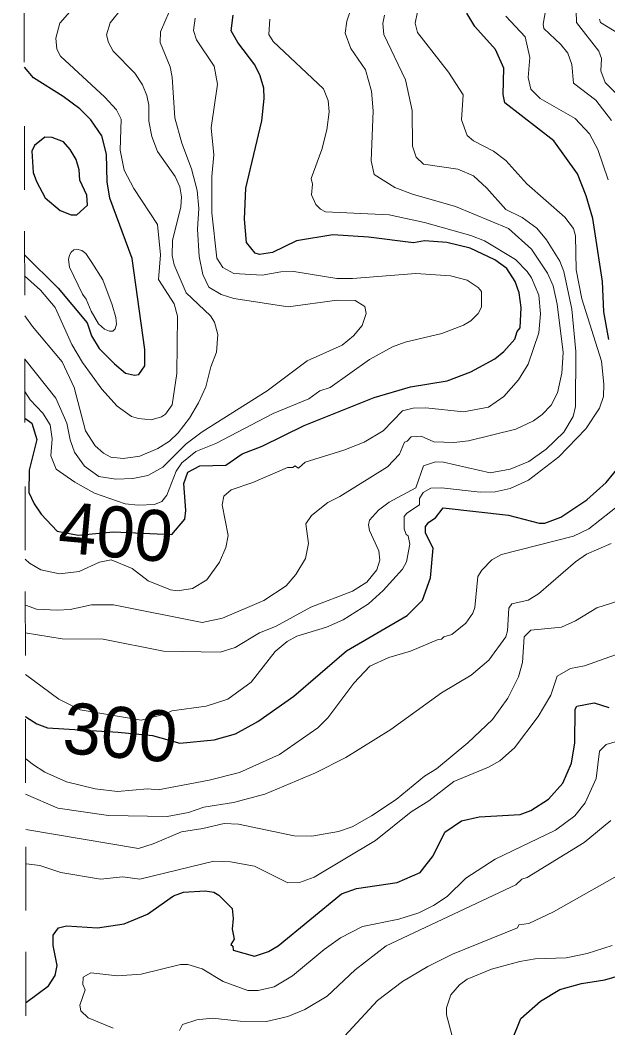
# Model space of a CAD drawing. Extents: x 474.5 to 500, y 7345.7 to 7373.4.
# Drawn here: x 474.522 to 475.444, y 7368.127 to 7369.706 of the extents above; entities that cross this region are included whole.
import ezdxf
from ezdxf.enums import TextEntityAlignment as Align

# ---------------------------------------------------------------- set-up
doc = ezdxf.new("R2010")
doc.units = 0
doc.header["$LTSCALE"] = 0.032
doc.linetypes.add('SHORT_DASHED', pattern=[2.7, 1.5, -1.2])
for name, color, linetype, lineweight in [('1', 7, 'Continuous', 25), ('2', 7, 'Continuous', 13), ('22', 7, 'SHORT_DASHED', 13)]:
    doc.layers.add(name, color=color, linetype=linetype, lineweight=lineweight)
doc.layers.add('61', color=7, linetype='Continuous')

msp = doc.modelspace()

# ---------------------------------------------------------------- linework, layer by layer
at = {"layer": '1'}
for points in [[(474.5297, 7369.0823), (474.5404, 7369.0743), (474.5484, 7369.0487), (474.5365, 7369.001), (474.536, 7368.9656), (474.5441, 7368.9481), (474.5553, 7368.9317), (474.5803, 7368.9051), (474.6132, 7368.8991), (474.6687, 7368.9043), (474.76, 7368.9001), (474.7807, 7368.9242), (474.7822, 7368.9378), (474.7792, 7368.9801), (474.7852, 7368.9977), (474.8039, 7369.0077), (474.8448, 7369.0087), (474.8706, 7369.0263), (474.9018, 7369.0383), (474.9677, 7369.071), (475.0773, 7369.1149), (475.1344, 7369.1314), (475.1918, 7369.141), (475.2292, 7369.155), (475.2667, 7369.1754), (475.2811, 7369.1868), (475.2981, 7369.206), (475.3017, 7369.2183), (475.3064, 7369.224), (475.3081, 7369.2559), (475.3049, 7369.2786), (475.2989, 7369.2968), (475.2856, 7369.3172), (475.2666, 7369.3304), (475.2279, 7369.3486), (475.1915, 7369.3579), (475.1567, 7369.3603), (475.1392, 7369.3572), (475.0684, 7369.366), (475.0125, 7369.3699), (474.9557, 7369.3604), (474.9178, 7369.3422), (474.8977, 7369.3389), (474.8911, 7369.3409), (474.8774, 7369.3577), (474.874, 7369.3942), (474.8764, 7369.443), (474.9011, 7369.5486), (474.9051, 7369.5834), (474.9044, 7369.5999), (474.8987, 7369.6188), (474.8901, 7369.6361), (474.8638, 7369.6712), (474.8533, 7369.6894), (474.8564, 7369.7143)], [(475.4455, 7369.2058), (475.438, 7369.2489), (475.4356, 7369.2968), (475.4204, 7369.3954), (475.41, 7369.4308), (475.3965, 7369.4656), (475.3592, 7369.5173), (475.2824, 7369.5769), (475.2801, 7369.5898), (475.2807, 7369.631), (475.2681, 7369.6603), (475.2352, 7369.6964), (475.2227, 7369.7173)], [(474.5293, 7369.3382), (474.5821, 7369.2861), (474.6275, 7369.2319), (474.634, 7369.2112), (474.6463, 7369.1918), (474.6704, 7369.1675), (474.6876, 7369.1529), (474.7014, 7369.1498), (474.7083, 7369.1508), (474.7177, 7369.1644), (474.7176, 7369.1899), (474.6978, 7369.3329), (474.6627, 7369.4272), (474.6586, 7369.4528), (474.6578, 7369.4962), (474.6505, 7369.5249), (474.6331, 7369.5501), (474.6158, 7369.5675), (474.5895, 7369.5868), (474.5432, 7369.6157), (474.5288, 7369.6323)], [(474.5306, 7368.6147), (474.5313, 7368.6142), (474.5482, 7368.6033), (474.5649, 7368.5968), (474.6758, 7368.5901), (474.7297, 7368.5847), (474.7726, 7368.5731), (474.8268, 7368.5781), (474.8599, 7368.5875), (474.895, 7368.6068), (474.9517, 7368.6467), (475.0341, 7368.7177), (475.1291, 7368.7732), (475.1532, 7368.7972), (475.166, 7368.8323), (475.17, 7368.8785), (475.1582, 7368.9022), (475.1581, 7368.9125), (475.1633, 7368.9195), (475.1738, 7368.9262), (475.1855, 7368.9419), (475.2885, 7368.9304), (475.3364, 7368.9176), (475.3452, 7368.9177), (475.3705, 7368.9273), (475.4112, 7368.9544), (475.4412, 7368.9813), (475.4773, 7369.0255)], [(474.5314, 7368.1664), (474.532, 7368.1669), (474.5667, 7368.1923), (474.5773, 7368.2086), (474.5804, 7368.2243), (474.5741, 7368.2557), (474.5741, 7368.2722), (474.5824, 7368.2834), (474.5948, 7368.2865), (474.6434, 7368.2834), (474.6855, 7368.29), (474.7222, 7368.3048), (474.7626, 7368.3337), (474.7783, 7368.3392), (474.8123, 7368.3413), (474.8261, 7368.3392), (474.8339, 7368.3346), (474.8547, 7368.3137), (474.8564, 7368.298), (474.8549, 7368.2814), (474.8579, 7368.2659), (474.8527, 7368.2572), (474.8557, 7368.2549), (474.8566, 7368.2484), (474.8899, 7368.239), (474.9117, 7368.2464), (474.9272, 7368.2553), (475.0264, 7368.3368), (475.0498, 7368.3449), (475.1136, 7368.3544), (475.1496, 7368.3701), (475.1699, 7368.3964), (475.1886, 7368.4335), (475.2143, 7368.4513), (475.2423, 7368.4572), (475.3067, 7368.4613), (475.3235, 7368.4674), (475.3511, 7368.4852), (475.3736, 7368.5102), (475.3869, 7368.5416), (475.3925, 7368.5734), (475.3926, 7368.6262), (475.3956, 7368.631), (475.4228, 7368.6359), (475.4455, 7368.6288)], [(475.2937, 7368.1065), (475.3075, 7368.1415), (475.3386, 7368.1686), (475.369, 7368.187), (475.403, 7368.1963), (475.4391, 7368.2021), (475.4732, 7368.2121)]]:
    msp.add_lwpolyline(points, dxfattribs=at)
msp.add_lwpolyline([(474.5428, 7369.4674), (474.5478, 7369.4533), (474.5617, 7369.428), (474.5849, 7369.4077), (474.6023, 7369.4012), (474.6111, 7369.4011), (474.6278, 7369.4162), (474.6267, 7369.4321), (474.6157, 7369.4555), (474.6148, 7369.4715), (474.61, 7369.4877), (474.6008, 7369.5035), (474.5902, 7369.5157), (474.5725, 7369.5222), (474.5608, 7369.523), (474.5447, 7369.5097), (474.5406, 7369.5007)], close=True, dxfattribs=at)
at = {"layer": '2'}
msp.add_line((474.5414, 7368.5398), (474.5307, 7368.5488), dxfattribs=at)
for points in [[(474.5293, 7369.3054), (474.5542, 7369.2828), (474.5769, 7369.2556), (474.6035, 7369.1979), (474.6198, 7369.1697), (474.6502, 7369.1279), (474.6744, 7369.1012), (474.697, 7369.0852), (474.708, 7369.0816), (474.7278, 7369.0795), (474.7439, 7369.0844), (474.7501, 7369.0887), (474.7608, 7369.1032), (474.7679, 7369.1524), (474.7688, 7369.242), (474.7637, 7369.2618), (474.7393, 7369.2997), (474.7424, 7369.3386), (474.7376, 7369.3858), (474.7007, 7369.4424), (474.6853, 7369.4711), (474.6793, 7369.5023), (474.6809, 7369.551), (474.6733, 7369.5656), (474.6551, 7369.5857), (474.5855, 7369.6497), (474.5798, 7369.6609), (474.5781, 7369.6781), (474.5845, 7369.7017), (474.621, 7369.7434)], [(474.5303, 7368.7893), (474.5324, 7368.7886), (474.5481, 7368.7832), (474.5805, 7368.7812), (474.6009, 7368.7827), (474.6341, 7368.7899), (474.6688, 7368.7899), (474.8077, 7368.7621), (474.8395, 7368.7689), (474.9046, 7368.7965), (474.9394, 7368.8196), (474.9544, 7368.8374), (474.9696, 7368.8623), (474.9745, 7368.8859), (474.9706, 7368.9165), (474.979, 7368.93), (475.0046, 7368.9502), (475.0238, 7368.9597), (475.0987, 7369.0063), (475.1171, 7369.026), (475.1253, 7369.045), (475.1295, 7369.0463), (475.1354, 7369.0529), (475.1514, 7369.054), (475.1711, 7369.0453), (475.2027, 7369.0444), (475.2253, 7369.0469), (475.2998, 7369.0652), (475.3274, 7369.0784), (475.3412, 7369.0882), (475.3554, 7369.1029), (475.3652, 7369.122), (475.3718, 7369.153), (475.3742, 7369.1854), (475.3647, 7369.2612), (475.3583, 7369.2899), (475.3494, 7369.3095), (475.3241, 7369.3473), (475.2883, 7369.3797), (475.205, 7369.4142), (475.1374, 7369.4334), (475.1101, 7369.4441), (475.0775, 7369.4641), (475.0726, 7369.4857), (475.0759, 7369.5639), (475.0734, 7369.5951), (475.064, 7369.6282), (475.0409, 7369.6617), (475.032, 7369.6859), (475.0349, 7369.7049), (475.0503, 7369.751)], [(475.4499, 7369.5488), (475.425, 7369.5807), (475.3904, 7369.6075), (475.3876, 7369.6369), (475.3815, 7369.6544), (475.3702, 7369.6682), (475.3437, 7369.693), (475.3425, 7369.6999), (475.3505, 7369.7454)], [(474.6826, 7369.726), (474.6633, 7369.7022), (474.6579, 7369.6835), (474.6607, 7369.6714), (474.6681, 7369.6577), (474.7021, 7369.6233), (474.7143, 7369.6047), (474.7209, 7369.5883), (474.724, 7369.5728), (474.7241, 7369.5481), (474.729, 7369.5241), (474.7379, 7369.5002), (474.7654, 7369.461), (474.7727, 7369.4451), (474.7751, 7369.4295), (474.7744, 7369.4136), (474.7611, 7369.3609), (474.7608, 7369.3375), (474.7637, 7369.3229), (474.7824, 7369.279), (474.8206, 7369.243), (474.8269, 7369.2328), (474.8325, 7369.2135), (474.83, 7369.1859), (474.8214, 7369.1628), (474.8137, 7369.1315), (474.8021, 7369.1064), (474.7877, 7369.0825), (474.7699, 7369.0594), (474.7566, 7369.0465), (474.7381, 7369.0346), (474.71, 7369.023), (474.6838, 7369.0189), (474.6643, 7369.0214), (474.653, 7369.0274), (474.6399, 7369.0391), (474.6249, 7369.0623), (474.6068, 7369.1304), (474.5883, 7369.1706), (474.5417, 7369.2258), (474.5294, 7369.2429), (474.5294, 7369.243)], [(474.5296, 7369.1746), (474.5782, 7369.1136), (474.5957, 7369.0745), (474.6006, 7369.0482), (474.6074, 7369.029), (474.6232, 7369.0073), (474.6457, 7368.9911), (474.6721, 7368.987), (474.6991, 7368.9878), (474.7227, 7368.9926), (474.7458, 7369.0055), (474.7824, 7369.0422), (474.8075, 7369.0607), (474.9099, 7369.125), (474.9722, 7369.1724), (475.0272, 7369.1969), (475.0451, 7369.2115), (475.0589, 7369.2277), (475.0648, 7369.2466), (475.0629, 7369.2575), (475.0477, 7369.267), (475.0195, 7369.2671), (474.9424, 7369.2567), (474.8575, 7369.27), (474.8376, 7369.2764), (474.8184, 7369.2877), (474.8086, 7369.3075), (474.8029, 7369.3358), (474.8006, 7369.3784), (474.8023, 7369.4108), (474.7997, 7369.4391), (474.7912, 7369.4731), (474.776, 7369.5133), (474.7648, 7369.5532), (474.7608, 7369.617), (474.7576, 7369.6329), (474.7417, 7369.6712), (474.7425, 7369.6881), (474.7562, 7369.7192)], [(474.5297, 7369.1241), (474.538, 7369.1109), (474.5577, 7369.0903), (474.5692, 7369.0718), (474.5725, 7369.0502), (474.5702, 7369.0233), (474.5785, 7369.0026), (474.6082, 7368.982), (474.6389, 7368.9646), (474.6867, 7368.9479), (474.7071, 7368.946), (474.7332, 7368.9473), (474.7446, 7368.9517), (474.7525, 7368.9619), (474.7669, 7368.9992), (474.7758, 7369.0124), (474.798, 7369.0299), (474.8292, 7369.0427), (474.9193, 7369.0898), (474.9751, 7369.1129), (474.9922, 7369.125), (475.0086, 7369.1304), (475.07, 7369.1743), (475.1064, 7369.1942), (475.1264, 7369.2016), (475.1838, 7369.2152), (475.2176, 7369.2282), (475.2291, 7369.235), (475.2409, 7369.2463), (475.2459, 7369.2564), (475.2458, 7369.2811), (475.2408, 7369.2871), (475.2234, 7369.2989), (475.1974, 7369.3054), (475.1427, 7369.3093), (475.0437, 7369.3014), (475.0191, 7369.3014), (474.9513, 7369.3125), (474.9312, 7369.3116), (474.9016, 7369.3063), (474.8575, 7369.3092), (474.8399, 7369.3185), (474.8308, 7369.3334), (474.823, 7369.4044), (474.823, 7369.4614), (474.8261, 7369.4949), (474.8221, 7369.5374), (474.8317, 7369.606), (474.8268, 7369.634), (474.7989, 7369.6756), (474.7943, 7369.6899), (474.7966, 7369.7095)], [(474.5301, 7368.8612), (474.5369, 7368.8549), (474.5544, 7368.8445), (474.584, 7368.8386), (474.6149, 7368.842), (474.6468, 7368.8565), (474.665, 7368.8601), (474.698, 7368.8468), (474.7229, 7368.8272), (474.7582, 7368.8134), (474.769, 7368.8115), (474.7927, 7368.8156), (474.8148, 7368.8289), (474.835, 7368.8564), (474.8446, 7368.8798), (474.8485, 7368.8982), (474.839, 7368.9464), (474.8419, 7368.9601), (474.8534, 7368.9702), (474.8871, 7368.9815), (474.9418, 7369.005), (474.9499, 7369.0052), (474.9533, 7369.0075), (474.9586, 7369.004), (474.9692, 7369.0134), (475.0302, 7369.0323), (475.0621, 7369.0447), (475.0915, 7369.0623), (475.1221, 7369.0941), (475.1387, 7369.0978), (475.1587, 7369.0987), (475.2176, 7369.0924), (475.2569, 7369.0995), (475.2811, 7369.1165), (475.304, 7369.1425), (475.319, 7369.1671), (475.3358, 7369.2162), (475.3383, 7369.246), (475.3356, 7369.2752), (475.3242, 7369.3024), (475.3177, 7369.3122), (475.299, 7369.331), (475.2508, 7369.3602), (475.2293, 7369.3685), (475.1565, 7369.389), (475.1009, 7369.401), (475.0011, 7369.4059), (474.9931, 7369.4098), (474.986, 7369.4174), (474.9792, 7369.4322), (474.9807, 7369.449), (474.9786, 7369.4581), (474.9954, 7369.5033), (475.0032, 7369.5342), (475.0072, 7369.5624), (475.0056, 7369.5805), (474.9983, 7369.5988), (474.9191, 7369.6726), (474.9125, 7369.684), (474.914, 7369.708)], [(475.0936, 7369.7142), (475.0911, 7369.7011), (475.0927, 7369.684), (475.1268, 7369.6127), (475.1373, 7369.5648), (475.1374, 7369.5085), (475.1433, 7369.4914), (475.1549, 7369.4807), (475.2089, 7369.4729), (475.2335, 7369.4621), (475.2543, 7369.4428), (475.2841, 7369.4096), (475.3098, 7369.3969), (475.3328, 7369.3801), (475.3481, 7369.3617), (475.3686, 7369.3284), (475.3751, 7369.3122), (475.3878, 7369.2532), (475.3941, 7369.187), (475.3934, 7369.1005), (475.3896, 7369.0852), (475.3749, 7369.0602), (475.3475, 7369.0337), (475.3202, 7369.0147), (475.2907, 7369.0022), (475.2594, 7368.9966), (475.1865, 7369.0134), (475.1735, 7369.0141), (475.1549, 7369.0076), (475.143, 7368.973), (475.1008, 7368.9505), (475.0842, 7368.9379), (475.0703, 7368.9224), (475.0687, 7368.9152), (475.0701, 7368.9062), (475.0851, 7368.8746), (475.0863, 7368.8597), (475.0819, 7368.8448), (475.0659, 7368.8254), (475.0437, 7368.8113), (474.9783, 7368.7862), (474.9228, 7368.756), (474.8977, 7368.7459), (474.8594, 7368.7228), (474.836, 7368.7158), (474.7471, 7368.7174), (474.6525, 7368.7357), (474.5882, 7368.7366), (474.5303, 7368.7458)], [(474.5304, 7368.6806), (474.5827, 7368.6421), (474.6164, 7368.6254), (474.7119, 7368.6092), (474.7494, 7368.6183), (474.7603, 7368.6236), (474.814, 7368.6309), (474.8478, 7368.642), (474.8845, 7368.6687), (474.922, 7368.7165), (474.9409, 7368.7322), (474.9564, 7368.7408), (475.003, 7368.7548), (475.0288, 7368.766), (475.0684, 7368.7911), (475.0917, 7368.8121), (475.1219, 7368.8455), (475.1285, 7368.857), (475.1333, 7368.8848), (475.1311, 7368.8978), (475.1279, 7368.9001), (475.1246, 7368.9089), (475.1246, 7368.9284), (475.1286, 7368.9335), (475.1484, 7368.9467), (475.1485, 7368.9566), (475.1546, 7368.9659), (475.1663, 7368.9726), (475.183, 7368.9734), (475.2436, 7368.9666), (475.2671, 7368.9671), (475.2907, 7368.9719), (475.3197, 7368.9853), (475.3672, 7369.0215), (475.4094, 7369.0654), (475.4312, 7369.098), (475.4372, 7369.1162), (475.438, 7369.1359), (475.4342, 7369.1715), (475.4033, 7369.2693), (475.3942, 7369.3151), (475.3935, 7369.3684), (475.39, 7369.3797), (475.3768, 7369.3976), (475.3168, 7369.4496), (475.2842, 7369.4863), (475.2647, 7369.5009), (475.2336, 7369.5172), (475.2235, 7369.5255), (475.2147, 7369.55), (475.217, 7369.5893), (475.1943, 7369.6248), (475.1453, 7369.6869), (475.1421, 7369.7017), (475.1453, 7369.7193)], [(475.2841, 7369.7124), (475.3144, 7369.6799), (475.3217, 7369.6478), (475.3192, 7369.6163), (475.3232, 7369.5981), (475.3378, 7369.5836), (475.393, 7369.5522), (475.4154, 7369.5283), (475.4285, 7369.5037), (475.4445, 7369.4558)], [(475.3942, 7369.7209), (475.3949, 7369.7028), (475.4297, 7369.6577), (475.4342, 7369.6462), (475.4333, 7369.6266), (475.44, 7369.6084), (475.4796, 7369.5693)], [(475.477, 7369.6754), (475.4327, 7369.7024), (475.4309, 7369.7077)], [(475.4659, 7368.9495), (475.4145, 7368.9088), (475.3903, 7368.8972), (475.2772, 7368.8687), (475.262, 7368.8603), (475.2463, 7368.8441), (475.2404, 7368.8341), (475.2354, 7368.7857), (475.2323, 7368.7766), (475.2215, 7368.761), (475.1994, 7368.7435), (475.187, 7368.7397), (475.1833, 7368.7358), (475.1778, 7368.7356), (475.1344, 7368.7174), (475.1003, 7368.707), (475.0707, 7368.6937), (475.0454, 7368.6672), (475.0046, 7368.6126), (474.9893, 7368.5972), (474.9288, 7368.5553), (474.8663, 7368.5267), (474.8185, 7368.5148), (474.7387, 7368.4996), (474.7219, 7368.5011), (474.6749, 7368.4972), (474.64, 7368.5016), (474.5951, 7368.5123), (474.561, 7368.5277), (474.5414, 7368.5398)], [(474.5308, 7368.4932), (474.5815, 7368.471), (474.6609, 7368.4597), (474.753, 7368.4581), (474.7865, 7368.4645), (474.8105, 7368.4725), (474.8567, 7368.4801), (474.9062, 7368.4932), (474.9855, 7368.5265), (475.0329, 7368.5503), (475.1036, 7368.5944), (475.1833, 7368.6518), (475.2296, 7368.6797), (475.2575, 7368.7028), (475.2839, 7368.7395), (475.2866, 7368.749), (475.2887, 7368.7844), (475.2935, 7368.7913), (475.3193, 7368.7972), (475.3354, 7368.8069), (475.3936, 7368.8571), (475.4106, 7368.8692), (475.4495, 7368.8857)], [(475.4945, 7368.8066), (475.427, 7368.7849), (475.3936, 7368.7649), (475.3716, 7368.7548), (475.3234, 7368.7503), (475.3129, 7368.7397), (475.3104, 7368.6996), (475.3038, 7368.6768), (475.2871, 7368.6437), (475.2631, 7368.6102), (475.2246, 7368.5733), (475.1753, 7368.5326), (475.1567, 7368.5213), (475.112, 7368.4846), (475.0734, 7368.4588), (475.0429, 7368.442), (475.0214, 7368.4343)], [(474.531, 7368.3841), (474.5323, 7368.3839), (474.553, 7368.381), (474.586, 7368.3701), (474.6482, 7368.36), (474.6832, 7368.3632), (474.7102, 7368.36), (474.8259, 7368.3878), (474.8523, 7368.387), (474.8898, 7368.38), (474.9419, 7368.3542), (474.9605, 7368.3544), (474.9836, 7368.3629), (475.0796, 7368.4204), (475.1355, 7368.4651), (475.1635, 7368.4825), (475.2026, 7368.513), (475.2567, 7368.5353), (475.2746, 7368.5453), (475.2974, 7368.5655), (475.3348, 7368.6147), (475.3548, 7368.6481), (475.3645, 7368.678), (475.3855, 7368.6902), (475.4072, 7368.6943), (475.4562, 7368.7113)], [(475.4719, 7368.5796), (475.4417, 7368.5707), (475.4309, 7368.5602), (475.4259, 7368.5175), (475.4084, 7368.4794), (475.3921, 7368.4592), (475.362, 7368.4364), (475.2673, 7368.391), (475.2211, 7368.3615), (475.1919, 7368.3325), (475.1706, 7368.3183), (475.1477, 7368.3069), (475.1163, 7368.2973), (475.0591, 7368.2857), (475.0245, 7368.2677), (474.9989, 7368.2494), (474.9494, 7368.208), (474.9206, 7368.1909), (474.8954, 7368.1851), (474.8794, 7368.1855), (474.8405, 7368.1996), (474.8078, 7368.2191), (474.785, 7368.2259), (474.7735, 7368.2259), (474.712, 7368.2106), (474.6749, 7368.2083), (474.6332, 7368.2131), (474.621, 7368.2061), (474.6204, 7368.1944), (474.6242, 7368.1865), (474.6156, 7368.1625), (474.6172, 7368.1536), (474.6289, 7368.1422), (474.6682, 7368.1261)], [(475.0214, 7368.4343), (474.9798, 7368.4271), (474.9521, 7368.4279), (474.8647, 7368.4461), (474.8422, 7368.4469), (474.8089, 7368.439), (474.7752, 7368.4341), (474.731, 7368.4153), (474.7079, 7368.408), (474.5309, 7368.4378)], [(474.772, 7368.1227), (474.777, 7368.1319), (474.7993, 7368.139), (474.8232, 7368.1421), (474.8671, 7368.1374), (474.9087, 7368.1369), (474.9423, 7368.1447), (474.969, 7368.1553), (475.0036, 7368.1761), (475.0477, 7368.2178), (475.0964, 7368.2553), (475.2998, 7368.3511), (475.3089, 7368.3595), (475.3177, 7368.3625), (475.4067, 7368.4173), (475.4486, 7368.4518)], [(475.4548, 7368.3631), (475.3588, 7368.3088), (475.3201, 7368.2902), (475.3043, 7368.2881), (475.3022, 7368.2833), (475.2006, 7368.2424), (475.1617, 7368.223), (475.1218, 7368.1991), (475.0828, 7368.1698), (475.0311, 7368.1135)], [(475.3301, 7368.2347), (475.3788, 7368.2364), (475.4115, 7368.243), (475.4509, 7368.2558)], [(475.1992, 7368.1158), (475.1908, 7368.1472), (475.1909, 7368.1582), (475.198, 7368.1786), (475.2115, 7368.194), (475.2236, 7368.2029), (475.2617, 7368.2187), (475.3059, 7368.2306), (475.3301, 7368.2347)]]:
    msp.add_lwpolyline(points, dxfattribs=at)
msp.add_lwpolyline([(474.6201, 7369.2767), (474.5996, 7369.319), (474.5982, 7369.3313), (474.5996, 7369.3378), (474.6021, 7369.3426), (474.6064, 7369.3463), (474.6109, 7369.3474), (474.619, 7369.3454), (474.6252, 7369.3403), (474.6348, 7369.3263), (474.6517, 7369.299), (474.6663, 7369.2599), (474.6725, 7369.2402), (474.6733, 7369.2295), (474.6714, 7369.2224), (474.6674, 7369.2188), (474.6626, 7369.2185), (474.6545, 7369.2219), (474.6449, 7369.2303), (474.6337, 7369.2503), (474.6258, 7369.2691)], close=True, dxfattribs=at)
at = {"layer": '22'}
msp.add_lwpolyline([(474.5381, 7364.3565), (474.5371, 7364.9213), (474.5361, 7365.4862), (474.5351, 7366.0511), (474.5341, 7366.616), (474.5331, 7367.1808), (474.5321, 7367.7457), (474.5311, 7368.3105), (474.5301, 7368.8754), (474.5291, 7369.4403), (474.5281, 7370.0051), (474.5272, 7370.57), (474.5262, 7371.1349), (474.5252, 7371.6997), (474.5242, 7372.2646), (474.5232, 7372.8295), (474.5222, 7373.3943)], dxfattribs=at)

# ---------------------------------------------------------------- texts
at = {"layer": '61'}
for s, rotation, p in [('400', 354.806, (474.6687, 7368.8642)), ('300', 354.958, (474.6758, 7368.55))]:
    msp.add_text(s, height=0.08, rotation=rotation, dxfattribs=at).set_placement(p, align=Align.CENTER)

doc.saveas('drawing.dxf')
